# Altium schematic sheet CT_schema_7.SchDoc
size 277 x 170 mm
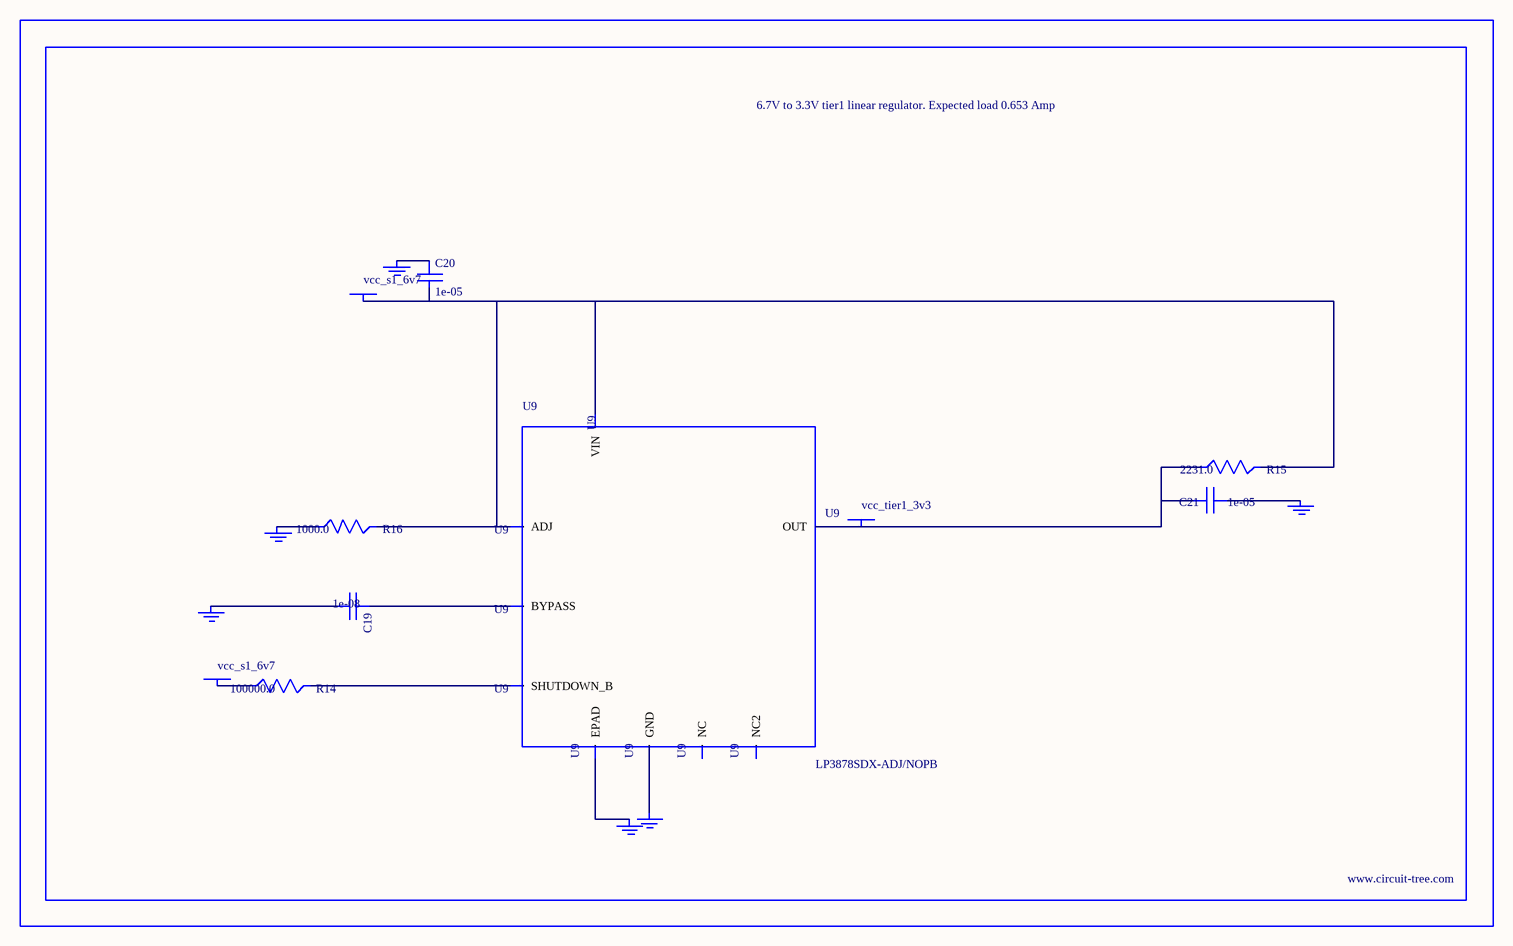
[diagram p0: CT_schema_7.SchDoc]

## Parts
BORDER6  (no value)
C19  1e-08  [C0402]
C20  1e-05  [C1206]
C21  1e-05  [C1210]
GND_INSTANCE_6_0  (no value)
GND_INSTANCE_6_1  (no value)
GND_INSTANCE_6_2  (no value)
GND_INSTANCE_6_3  (no value)
GND_INSTANCE_6_4  (no value)
GND_INSTANCE_6_5  (no value)
POWER_INSTANCE_6_0  vcc_s1_6v7
POWER_INSTANCE_6_1  vcc_s1_6v7
POWER_INSTANCE_6_2  vcc_tier1_3v3
R14  100000.0  [R0603]
R15  2231.0  [R0603]
R16  1000.0  [R0603]
U9  LP3878SDX-ADJ/NOPB  [WSON-8]

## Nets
NetC19_1: C19.1 U9.1(BYPASS)
NetC19_2: C19.2 GND_INSTANCE_6_0.0(GND)
NetC20_1: C20.1 GND_INSTANCE_6_1.0(GND)
NetC20_2: C20.2 POWER_INSTANCE_6_0.0(PWR) R15.2 R16.2 U9.4(VIN) U9.6(ADJ)
NetC21_1: C21.1 GND_INSTANCE_6_2.0(GND)
NetC21_2: C21.2 POWER_INSTANCE_6_2.0(PWR) R15.1 U9.5(OUT)
NetGND_INSTANCE_6_3_0: GND_INSTANCE_6_3.0(GND) R16.1
NetGND_INSTANCE_6_4_0: GND_INSTANCE_6_4.0(GND) U9.PAD(EPAD)
NetGND_INSTANCE_6_5_0: GND_INSTANCE_6_5.0(GND) U9.3(GND)
NetPOWER_INSTANCE_6_1_0: POWER_INSTANCE_6_1.0(PWR) R14.1
NetR14_2: R14.2 U9.8(SHUTDOWN_B)

Not connected (* = marked no-connect by the designer): U9 2(NC) 7(NC2)

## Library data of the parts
BORDER6 = BORDER_PAGE6
C19 = C0402C103K3RAC
C20 = C1206C106K3RACTU
C21 = GRM32DR61E106MA12L
GND_INSTANCE_6_0-GND_INSTANCE_6_5 = GND
POWER_INSTANCE_6_0-POWER_INSTANCE_6_2 = PWR
R14 = RC0603JR-07100KL
R15 = R15
R16 = RC0603JR-071KL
